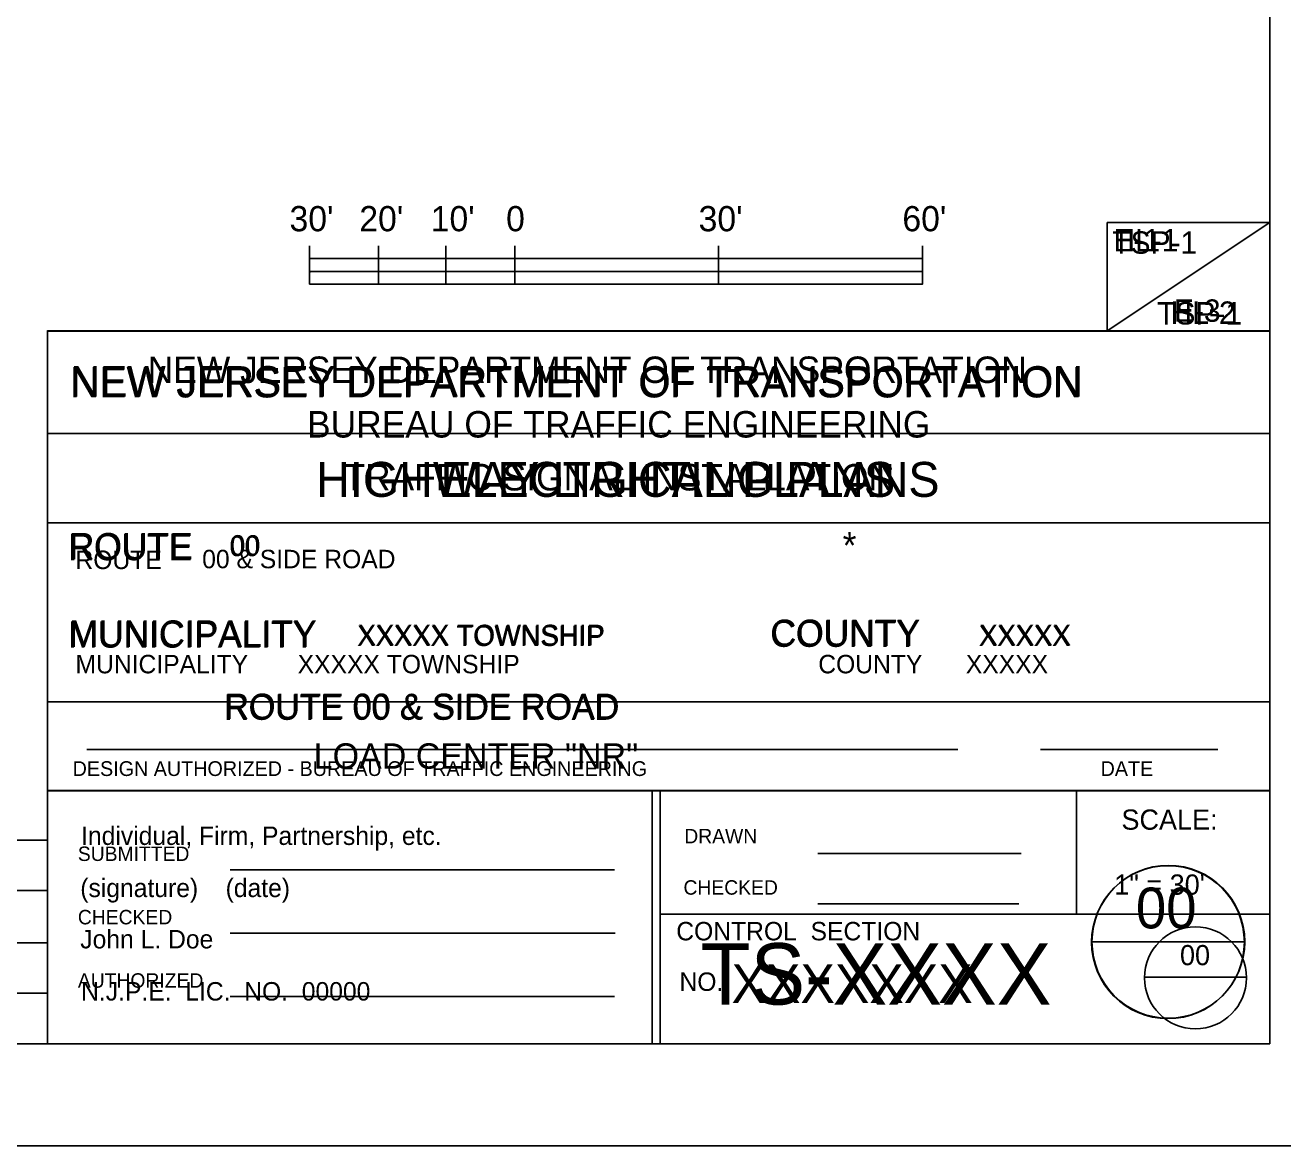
# Model space of a CAD drawing. Extents: x 488740 to 507913, y 466518 to 497949.
# Drawn here: x 507910.118 to 507910.636, y 496046.406 to 496046.865 of the extents above; entities that cross this region are included whole.
import ezdxf

# ---------------------------------------------------------------- set-up
doc = ezdxf.new("R2010")
doc.units = 0
for name, color, linetype in [('1', 7, 'Continuous'), ('11', 7, 'Continuous'), ('25', 7, 'Continuous'), ('26', 7, 'Continuous'), ('27', 7, 'Continuous'), ('38', 7, 'Continuous'), ('9', 7, 'Continuous')]:
    doc.layers.add(name, color=color, linetype=linetype)

msp = doc.modelspace()

# ---------------------------------------------------------------- linework, layer by layer
at = {"layer": '1'}
for p, q in [((507910.6273, 496046.44783), (507910.6273, 496048.19783)), ((507910.6273, 496046.44783), (507910.6273, 496046.80647)), ((507910.23454, 496046.75859), (507910.23454, 496046.77434)), ((507910.26276, 496046.75859), (507910.26276, 496046.77434)), ((507910.29032, 496046.75859), (507910.29032, 496046.77434)), ((507910.31853, 496046.75859), (507910.31853, 496046.77434)), ((507910.40186, 496046.75859), (507910.40186, 496046.77434)), ((507910.4852, 496046.75859), (507910.4852, 496046.77434)), ((507910.23454, 496046.76909), (507910.4852, 496046.76909)), ((507910.23454, 496046.75859), (507910.4852, 496046.75859)), ((507907.8773, 496046.44783), (507910.6273, 496046.44783)), ((507910.63583, 496046.40617), (507907.72408, 496046.40617))]:
    msp.add_line(p, q, dxfattribs=at)
for points in [[(507910.26276, 496046.76384), (507910.29032, 496046.76384), (507910.29032, 496046.76909), (507910.26276, 496046.76909)], [(507910.31853, 496046.76384), (507910.40186, 496046.76384), (507910.40186, 496046.76909), (507910.31853, 496046.76909)], [(507910.23454, 496046.75859), (507910.26276, 496046.75859), (507910.26276, 496046.76384), (507910.23454, 496046.76384)], [(507910.29032, 496046.76384), (507910.31853, 496046.76384), (507910.31853, 496046.75859), (507910.29032, 496046.75859)], [(507910.40186, 496046.76384), (507910.4852, 496046.76384), (507910.4852, 496046.75859), (507910.40186, 496046.75859)]]:
    msp.add_lwpolyline(points, close=True, dxfattribs=at)
for points in [[(507910.23454, 496046.76351), (507910.2352, 496046.76384)], [(507910.26276, 496046.75859), (507910.26276, 496046.75859)]]:
    msp.add_lwpolyline(points, dxfattribs=at)
at = {"layer": '25'}
for p, q in [((507910.5607, 496046.7395), (507910.6273, 496046.78379)), ((507910.5607, 496046.78379), (507910.6273, 496046.78379)), ((507910.5607, 496046.78379), (507910.5607, 496046.7395)), ((507910.1273, 496046.44783), (507910.1273, 496046.7395)), ((507910.6273, 496046.7395), (507910.1273, 496046.7395)), ((507910.1273, 496046.69751), (507910.6273, 496046.69751)), ((507910.6273, 496046.55151), (507910.1273, 496046.55151)), ((507910.37467, 496046.55151), (507910.37467, 496046.44783)), ((507910.58563, 496046.4895), (507910.55479, 496046.4895)), ((507910.58563, 496046.4895), (507910.6168, 496046.4895))]:
    msp.add_line(p, q, dxfattribs=at)
msp.add_circle((507910.58579, 496046.48959), 0.03125, dxfattribs=at)
at = {"layer": '26'}
for p, q in [((507910.5607, 496046.78379), (507910.6273, 496046.78379)), ((507910.5607, 496046.78379), (507910.5607, 496046.7395)), ((507910.5607, 496046.7395), (507910.6273, 496046.78379)), ((507910.1273, 496046.44783), (507910.1273, 496046.7395)), ((507910.6273, 496046.7395), (507910.1273, 496046.7395)), ((507910.1273, 496046.69751), (507910.6273, 496046.69751)), ((507910.58563, 496046.4895), (507910.55479, 496046.4895)), ((507910.58563, 496046.4895), (507910.6168, 496046.4895))]:
    msp.add_line(p, q, dxfattribs=at)
msp.add_circle((507910.58564, 496046.48943), 0.03125, dxfattribs=at)
at = {"layer": '27'}
for p, q in [((507910.5607, 496046.78379), (507910.6273, 496046.78379)), ((507910.5607, 496046.78379), (507910.5607, 496046.7395)), ((507910.5607, 496046.7395), (507910.6273, 496046.78379)), ((507910.6271, 496046.73938), (507910.1271, 496046.73938)), ((507910.1273, 496046.44783), (507910.1273, 496046.7395)), ((507910.6271, 496046.66096), (507910.1271, 496046.66096)), ((507910.6271, 496046.5878), (507910.1271, 496046.5878)), ((507910.14337, 496046.56824), (507910.49967, 496046.56824)), ((507910.53346, 496046.56824), (507910.60597, 496046.56824)), ((507910.6271, 496046.55138), (507910.1271, 496046.55138)), ((507910.37795, 496046.44783), (507910.37795, 496046.55151)), ((507910.54823, 496046.50098), (507910.54823, 496046.55151)), ((507909.68861, 496046.53117), (507910.1273, 496046.53117)), ((507910.44247, 496046.52575), (507910.52559, 496046.52575)), ((507910.2021, 496046.51903), (507910.35925, 496046.51903)), ((507910.2021, 496046.51903), (507910.35925, 496046.51903)), ((507909.68861, 496046.5105), (507910.1273, 496046.5105)), ((507910.6271, 496046.50086), (507910.37776, 496046.50086)), ((507910.44247, 496046.50509), (507910.52461, 496046.50509)), ((507910.2021, 496046.49311), (507910.35958, 496046.49311)), ((507910.2021, 496046.49311), (507910.35958, 496046.49311)), ((507909.68861, 496046.48917), (507910.1273, 496046.48917)), ((507910.57601, 496046.47507), (507910.61778, 496046.47507)), ((507909.68861, 496046.4685), (507910.1273, 496046.4685)), ((507910.2021, 496046.46719), (507910.35925, 496046.46719))]:
    msp.add_line(p, q, dxfattribs=at)
msp.add_circle((507910.59687, 496046.47484), 0.02087, dxfattribs=at)

# ---------------------------------------------------------------- texts
at = {"layer": '1'}
for s, height, p in [("30'", 0.010317, (507910.22634, 496046.78024)), ("20'", 0.010317, (507910.25488, 496046.78024)), ("10'", 0.010317, (507910.28408, 496046.78024)), ('0', 0.01032, (507910.31492, 496046.78024)), ("30'", 0.010317, (507910.39366, 496046.78024)), ("60'", 0.010317, (507910.477, 496046.78024))]:
    msp.add_text(s, height=height, dxfattribs=at).set_placement(p)
at = {"layer": '11'}
for s, height, p in [('HL-1', 0.009167, (507910.56332, 496046.77198)), ('HL-2', 0.009167, (507910.58672, 496046.74237)), ('HIGHWAY LIGHTING PLANS', 0.0142992, (507910.2372, 496046.67159))]:
    msp.add_text(s, height=height, dxfattribs=at).set_placement(p)
at = {"layer": '25'}
for s, height, p in [('NEW JERSEY DEPARTMENT OF TRANSPORTATION', 0.0124665, (507910.13681, 496046.7126)), ('ROUTE', 0.010827, (507910.13615, 496046.646)), ('00                      ', 0.0082992, (507910.2021, 496046.64764)), ('*', 0.01083, (507910.45257, 496046.64633)), ('MUNICIPALITY', 0.0108268, (507910.13615, 496046.61024)), ('XXXXX TOWNSHIP    ', 0.0083996, (507910.25427, 496046.61089)), ('COUNTY', 0.010827, (507910.42323, 496046.61056)), ('XXXXX        ', 0.0083996, (507910.50853, 496046.61089)), ('             ROUTE 00 & SIDE ROAD            ', 0.0103996, (507910.14958, 496046.58071)), ('CONTROL  SECTION', 0.0075453, (507910.38451, 496046.49016)), ('XXXXXXX  ', 0.015797, (507910.40712, 496046.46457)), ('NO.', 0.007545, (507910.38583, 496046.46949))]:
    msp.add_text(s, height=height, dxfattribs=at).set_placement(p)
at = {"layer": '26'}
for s, height, p in [('NEW JERSEY DEPARTMENT OF TRANSPORTATION', 0.0124665, (507910.13648, 496046.71227)), ('ROUTE', 0.010827, (507910.13583, 496046.64567)), ('00                      ', 0.0082992, (507910.20177, 496046.64731)), ('*', 0.01083, (507910.45258, 496046.64633)), ('MUNICIPALITY', 0.0108268, (507910.13583, 496046.60991)), ('XXXXX TOWNSHIP    ', 0.0083996, (507910.25394, 496046.61056)), ('COUNTY', 0.010827, (507910.4229, 496046.61024)), ('XXXXX        ', 0.0083996, (507910.5082, 496046.61056)), ('             ROUTE 00 & SIDE ROAD            ', 0.0103996, (507910.14928, 496046.58038)), ('               LOAD CENTER "NR"              ', 0.0103996, (507910.17827, 496046.56037)), ('Individual, Firm, Partnership, etc.', 0.0075453, (507910.14108, 496046.5292)), ('(signature)    (date)', 0.0075453, (507910.14075, 496046.50787)), ('00', 0.016665, (507910.57251, 496046.49508)), ('John L. Doe', 0.0075453, (507910.14075, 496046.48688)), ('N.J.P.E.  LIC.  NO.  00000', 0.0075453, (507910.14108, 496046.46555))]:
    msp.add_text(s, height=height, dxfattribs=at).set_placement(p)
at = {"layer": '27'}
for s, height, p in [('NEW JERSEY DEPARTMENT OF TRANSPORTATION', 0.0108268, (507910.16831, 496046.71818)), ('BUREAU OF TRAFFIC ENGINEERING', 0.0108268, (507910.23349, 496046.69587)), ('TRAFFIC SIGNAL INSTALLATION', 0.0108268, (507910.24836, 496046.67421)), ('ROUTE', 0.007545, (507910.13878, 496046.64206)), ('00 & SIDE ROAD                                          ', 0.0075453, (507910.19062, 496046.64239)), ('MUNICIPALITY', 0.0075453, (507910.13878, 496046.59941)), ('XXXXX TOWNSHIP             ', 0.0075453, (507910.22966, 496046.59941)), ('COUNTY', 0.007545, (507910.44259, 496046.59941)), ('XXXXX          ', 0.0075453, (507910.50295, 496046.59941)), ('DESIGN AUTHORIZED - BUREAU OF TRAFFIC ENGINEERING             ', 0.0060354, (507910.13762, 496046.55741)), ('DATE', 0.006035, (507910.55807, 496046.55741)), ('SCALE:', 0.008268, (507910.5666, 496046.53543)), ('DRAWN', 0.005906, (507910.3878, 496046.52986)), ('SUBMITTED                           ', 0.0059055, (507910.13976, 496046.52264)), ('1" = 30\'', 0.008268, (507910.56365, 496046.50886)), ('CHECKED', 0.005906, (507910.38747, 496046.50886)), ('CHECKED                            ', 0.0059055, (507910.13976, 496046.49672)), ('TS-XXXX', 0.025098, (507910.39436, 496046.46391)), ('00', 0.008268, (507910.59055, 496046.47999)), ('AUTHORIZED                          ', 0.0059055, (507910.13976, 496046.4708))]:
    msp.add_text(s, height=height, dxfattribs=at).set_placement(p)
at = {"layer": '38'}
for p in [(507910.56285, 496046.77105), (507910.58119, 496046.7421)]:
    msp.add_text('TSP-1', height=0.009167, dxfattribs=at).set_placement(p)
at = {"layer": '9'}
for s, height, p in [('E-1', 0.009167, (507910.56332, 496046.77198)), ('E-1', 0.009167, (507910.56332, 496046.77198)), ('E-3', 0.009167, (507910.58809, 496046.7432)), ('ELECTRICAL PLANS', 0.0142992, (507910.28806, 496046.67159))]:
    msp.add_text(s, height=height, dxfattribs=at).set_placement(p)

doc.saveas('drawing.dxf')
